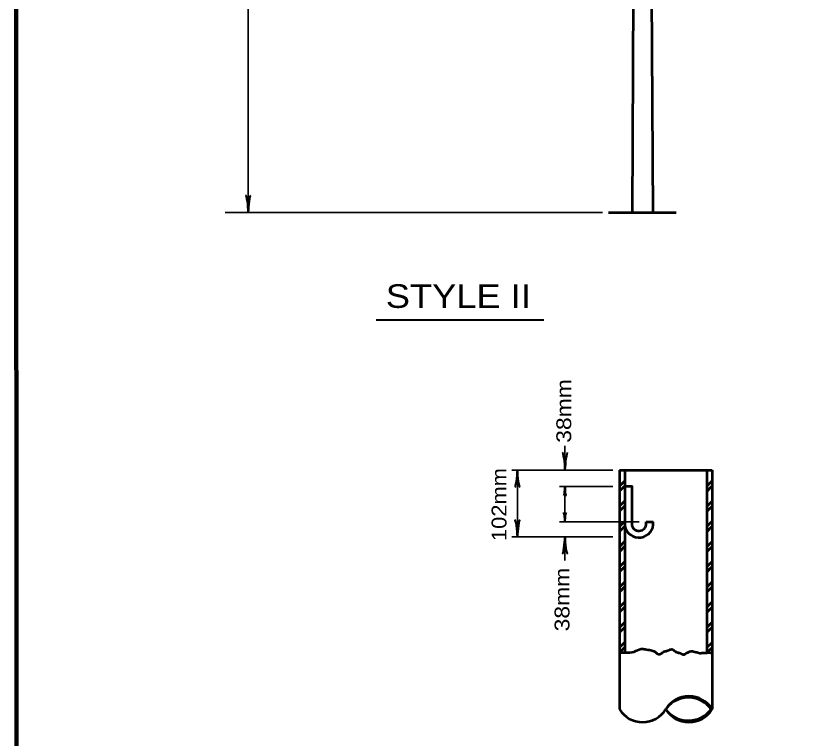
# Model space of a CAD drawing. Extents: x 6460 to 7173, y 270 to 723.
# Drawn here: x 6508.1 to 6645, y 436 to 558.5 of the extents above; entities that cross this region are included whole.
import ezdxf

# ---------------------------------------------------------------- set-up
doc = ezdxf.new("R2010")
doc.units = 0
doc.layers.add('1', color=7, linetype='Continuous', lineweight=35)

msp = doc.modelspace()

# ---------------------------------------------------------------- linework, layer by layer
at = {"layer": '1'}
for p, q in [((6547.486, 674.006), (6547.486, 525.256)), ((6607.592, 525.256), (6543.592, 525.256)), ((6601.205, 481.646), (6601.205, 485.666)), ((6609.325, 481.566), (6592.205, 481.566)), ((6593.145, 481.566), (6593.145, 470.266)), ((6609.325, 478.806), (6600.265, 478.806)), ((6601.205, 478.806), (6601.205, 472.806)), ((6613.825, 472.806), (6600.265, 472.806)), ((6609.325, 470.266), (6592.205, 470.266)), ((6601.205, 470.246), (6601.205, 466.226))]:
    msp.add_line(p, q, dxfattribs=at)
at = {"layer": '1', "lineweight": 53}
for p, q in [((6615.342, 653.756), (6616.092, 525.256)), ((6613.322, 650.256), (6612.592, 525.256)), ((6608.592, 525.256), (6620.092, 525.256)), ((6610.445, 481.546), (6626.165, 481.546)), ((6611.345, 481.546), (6611.345, 450.646)), ((6625.265, 481.546), (6625.265, 450.606)), ((6626.165, 481.546), (6626.165, 441.026)), ((6610.445, 478.846), (6611.345, 479.766)), ((6625.265, 478.826), (6626.165, 479.746)), ((6610.445, 478.006), (6611.345, 478.906)), ((6625.265, 477.966), (6626.165, 478.886)), ((6610.445, 475.426), (6611.345, 476.346)), ((6625.265, 475.406), (6626.165, 476.306)), ((6610.445, 474.586), (6611.345, 475.486)), ((6625.265, 474.546), (6626.165, 475.466)), ((6610.445, 472.006), (6611.345, 472.926)), ((6614.985, 472.786), (6616.185, 472.786)), ((6625.265, 471.986), (6626.165, 472.886)), ((6610.445, 471.146), (6611.345, 472.066)), ((6625.265, 471.126), (6626.165, 472.046)), ((6610.445, 468.586), (6611.345, 469.506)), ((6625.265, 468.566), (6626.165, 469.466)), ((6610.445, 467.726), (6611.345, 468.646)), ((6625.265, 467.706), (6626.165, 468.626)), ((6610.445, 465.166), (6611.345, 466.066)), ((6625.265, 465.146), (6626.165, 466.046)), ((6610.445, 464.306), (6611.345, 465.226)), ((6625.265, 464.286), (6626.165, 465.206)), ((6610.445, 461.746), (6611.345, 462.646)), ((6625.265, 461.726), (6626.165, 462.626)), ((6610.445, 460.886), (6611.345, 461.806)), ((6625.265, 460.866), (6626.165, 461.766)), ((6610.445, 458.326), (6611.345, 459.226)), ((6625.265, 458.306), (6626.165, 459.206)), ((6610.445, 457.466), (6611.345, 458.386)), ((6625.265, 457.446), (6626.165, 458.346)), ((6610.445, 454.906), (6611.345, 455.806)), ((6625.265, 454.886), (6626.165, 455.786)), ((6610.445, 454.046), (6611.345, 454.966)), ((6625.265, 454.026), (6626.165, 454.926)), ((6610.445, 451.486), (6611.345, 452.386)), ((6625.265, 451.466), (6626.165, 452.366)), ((6610.445, 450.626), (6611.345, 451.526)), ((6625.265, 450.606), (6626.165, 451.506)), ((6620.125, 442.726), (6620.185, 442.586)), ((6620.685, 442.966), (6620.765, 442.806)), ((6624.045, 442.866), (6623.945, 442.666)), ((6624.585, 442.586), (6624.485, 442.406)), ((6624.985, 440.026), (6625.085, 439.826)), ((6625.465, 440.406), (6625.565, 440.246)), ((6622.045, 439.086), (6622.205, 438.826)), ((6622.725, 439.126), (6622.865, 438.866))]:
    msp.add_line(p, q, dxfattribs=at)
at = {"layer": '1', "lineweight": 40}
msp.add_line((6569.204, 507.054), (6597.626, 507.054), dxfattribs=at)
at = {"layer": '1', "lineweight": 158}
msp.add_lwpolyline([(7167.871, 717.799), (6508.121, 717.715), (6508.204, 279.382)], dxfattribs=at)
at = {"layer": '1', "lineweight": 53}
for points in [[(6610.445, 481.546), (6610.445, 450.626), (6610.445, 441.026)], [(6611.345, 478.826), (6612.565, 478.826), (6612.565, 472.186)]]:
    msp.add_lwpolyline(points, dxfattribs=at)
for centre, radius, start, end in [((6613.765, 472.566), 2.435, 190.86929, 5.14039), ((6613.764, 472.512), 1.247, 195.45934, 12.61314), ((6622.238, 438.625), 4.61, 31.48112, 148.51888), ((6622.152, 438.228), 4.781, 35.97027, 140.35792), ((6614.376, 443.44), 4.61, 211.48112, 328.51888), ((6622.238, 443.44), 4.61, 211.48112, 328.51888), ((6622.138, 443.948), 4.854, 221.44282, 323.1281)]:
    msp.add_arc(centre, radius, start, end, dxfattribs=at)
at = {"layer": '1', "lineweight": 40}
for centre, major_axis, ratio, start_param, end_param in [((6547.21, 526.347), (0.156, -1.786), 0.122415, 0.8963533, 3.1415927), ((6547.698, 526.377), (-0.176, -1.756), 0.07063, 3.1407148, 5.41811), ((6600.935, 482.738), (0.157, -1.8), 0.122415, 0.8963533, 3.1415927), ((6601.427, 482.767), (-0.177, -1.77), 0.07063, 3.1407148, 5.41811), ((6592.931, 480.438), (0.177, 1.77), 0.07063, 3.1407148, 5.41811), ((6593.423, 480.468), (-0.157, 1.8), 0.122415, 0.8963533, 3.1415927), ((6601.186, 479.019), (0.177, 1.77), 0.07063, 3.1407148, 3.8293255), ((6601.004, 477.66), (0.177, 1.77), 0.07063, 4.7093373, 5.41811), ((6601.495, 477.69), (-0.157, 1.8), 0.122415, 0.8963533, 1.5837952), ((6601.298, 479.038), (-0.157, 1.8), 0.122415, 2.4431075, 3.1415927), ((6601.174, 472.581), (0.177, -1.77), 0.07063, 2.4538598, 3.1424706), ((6600.992, 473.939), (0.177, -1.77), 0.07063, 0.8650754, 1.573848), ((6601.484, 473.91), (-0.157, -1.8), 0.122415, 4.6993901, 5.386832), ((6601.287, 472.561), (-0.157, -1.8), 0.122415, 3.1415927, 3.8400778), ((6592.866, 471.363), (0.157, -1.8), 0.122415, 0.8963533, 3.1415927), ((6593.358, 471.392), (-0.177, -1.77), 0.07063, 3.1407148, 5.41811), ((6601, 469.121), (0.177, 1.77), 0.07063, 3.1407148, 5.41811), ((6601, 469.121), (0.177, 1.77), 0.07063, 3.1407148, 5.41811), ((6601.492, 469.15), (-0.157, 1.8), 0.122415, 0.8963533, 3.1415927), ((6601.492, 469.15), (-0.157, 1.8), 0.122415, 0.8963533, 3.1415927)]:
    msp.add_ellipse(centre, major_axis=major_axis, ratio=ratio, start_param=start_param, end_param=end_param, dxfattribs=at)
at = {"layer": '1', "lineweight": 53}
msp.add_spline([(6610.445, 450.626), (6611.445, 450.646), (6612.965, 450.786), (6614.125, 451.246), (6614.825, 451.206), (6615.805, 451.026), (6616.405, 450.826), (6616.845, 450.466), (6617.185, 450.346), (6617.505, 450.466), (6618.065, 450.806), (6618.665, 450.986), (6619.345, 451.186), (6619.885, 450.866), (6620.205, 450.686), (6620.805, 450.526), (6621.425, 450.286), (6621.625, 450.426), (6622.185, 450.706), (6622.645, 450.866), (6623.425, 450.726), (6623.725, 450.646), (6624.085, 450.546), (6624.445, 450.566), (6624.845, 450.566), (6625.305, 450.606), (6625.545, 450.646), (6625.985, 450.586), (6626.165, 450.586)], degree=3, dxfattribs=at)

# ---------------------------------------------------------------- texts
at = {"layer": '1', "width": 1.15}
msp.add_text('STYLE II', height=4, dxfattribs=at).set_placement((6570.824, 509.063))
at = {"layer": '1'}
for s, width, p in [('38mm', 1.15, (6602.273, 486.198)), ('102mm', 1.1, (6591.293, 469.542)), ('38mm', 1.15, (6601.977, 454.23))]:
    msp.add_text(s, height=2.52, rotation=90, dxfattribs=dict(at, width=width)).set_placement(p)

doc.saveas('drawing.dxf')
